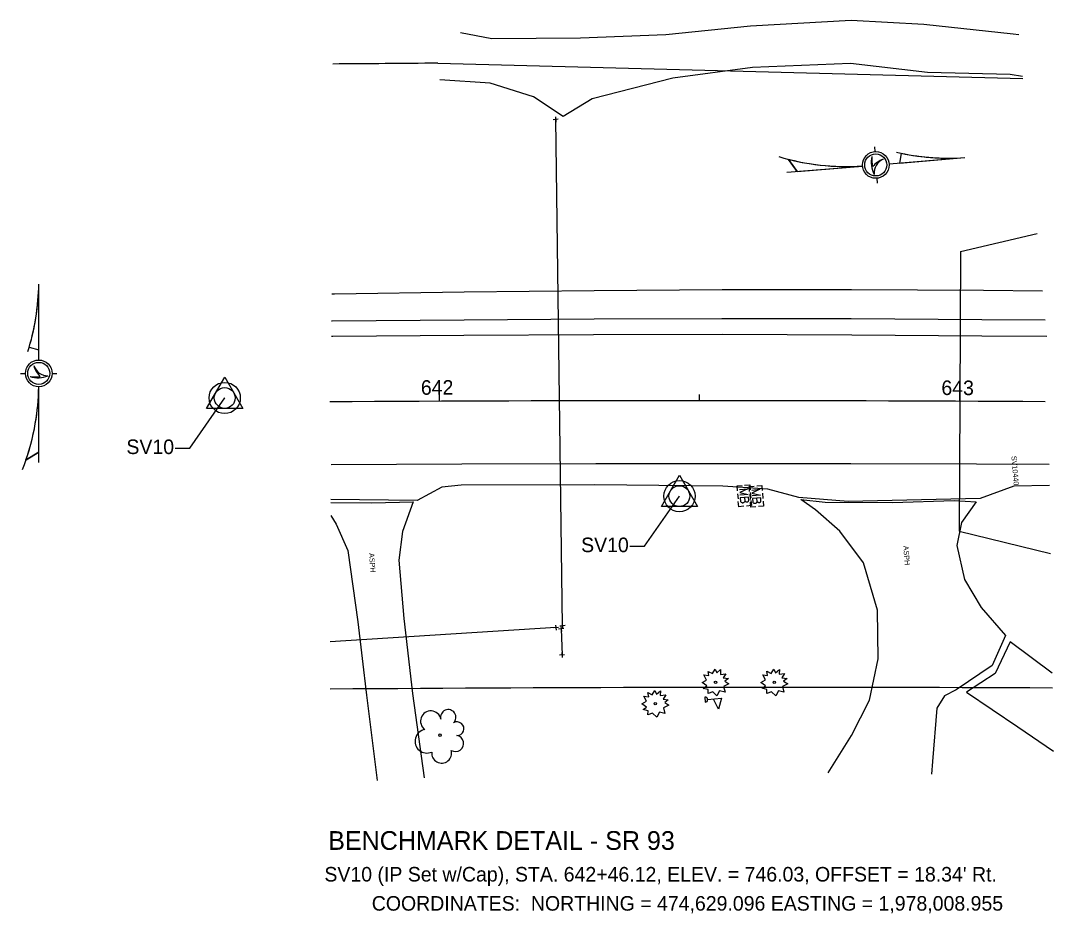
# Model space of a CAD drawing. Extents: x 0 to 2009, y -63 to 801.
# Drawn here: x 698.2 to 896.7, y 252.2 to 423.9 of the extents above; entities that cross this region are included whole.
import ezdxf

# ---------------------------------------------------------------- set-up
doc = ezdxf.new("R2010")
doc.units = 0
for name, color, linetype in [('Default', 7, 'Continuous'), ('DR_X_Elev_Flow', 7, 'Continuous'), ('DR_X_Storm_Sewer', 7, 'Continuous'), ('DV_X_Section_VMS_Line', 7, 'Continuous'), ('HY_X_Water_Edge', 7, 'Continuous'), ('PF_X_Text', 7, 'Continuous'), ('PV_X_Driveway', 7, 'Continuous'), ('PV_X_Shoulder', 7, 'Continuous'), ('PV_X_Shoulder_Aggregate', 7, 'Continuous'), ('PV_X_Text', 7, 'Continuous'), ('RD_X_Cells', 7, 'Continuous'), ('RD_X_GR_Lt', 7, 'Continuous'), ('RW_P_Const_Limits', 7, 'Continuous'), ('RW_X_CL_500_Stations', 7, 'Continuous'), ('RW_X_Esmt_SH', 7, 'Continuous'), ('SV_P_Control_Cells_Set', 7, 'Continuous'), ('SV_X_Control_Cells_Found', 7, 'Continuous'), ('TX_P_1', 7, 'Continuous'), ('UT_X_Electric', 7, 'Continuous'), ('UT_X_Electric_Cells', 7, 'Continuous'), ('VG_X_Cells', 7, 'Continuous')]:
    doc.layers.add(name, color=color, linetype=linetype)

msp = doc.modelspace()

# ---------------------------------------------------------------- linework, layer by layer
at = {"layer": 'Default'}
for p, q in [((730.73, 341.71), (737.42, 351.34)), ((727.91, 341.71), (730.73, 341.71)), ((818.12, 322.85), (824.8, 332.47)), ((815.3, 322.85), (818.12, 322.85))]:
    msp.add_line(p, q, dxfattribs=at)
at = {"layer": 'DR_X_Elev_Flow'}
for points in [[(895.1, 366.33), (882.95, 366.37), (857.78, 366.57), (832.95, 366.55), (808.41, 366.52), (783.46, 366.31), (758.09, 366.09), (757.96, 366.09)], [(895.91, 334.5), (889.06, 334.41), (882.58, 332), (857.24, 331.41), (847.74, 332.18), (841.82, 333.81), (833.16, 334.37), (808.52, 334.66), (782.86, 334.55), (779.12, 334.2), (774.42, 331.65), (757.82, 331.79)]]:
    msp.add_lwpolyline(points, dxfattribs=at)
at = {"layer": 'DV_X_Section_VMS_Line'}
for p, q in [((835.99, 332.93), (836.08, 331.94)), ((837.25, 332.52), (837.25, 332.52)), ((838.33, 332.82), (838.41, 331.82)), ((838.43, 333.13), (838.51, 332.14)), ((839.59, 332.41), (839.59, 332.41)), ((840.77, 333.02), (840.85, 332.02)), ((829.69, 293.82), (829.77, 292.82)), ((830.23, 293.36), (832.92, 293.58)), ((832.29, 291.52), (831.33, 293.45)), ((831.33, 293.45), (831.33, 293.45)), ((832.92, 293.58), (832.29, 291.52))]:
    msp.add_line(p, q, dxfattribs=at)
for points in [[(835.95, 333.45), (835.87, 334.42), (836.84, 334.5)], [(836.35, 333.75), (837.94, 333.88), (836.4, 333.17), (838.04, 332.75), (836.44, 332.62)], [(837.34, 334.54), (838.31, 334.62), (838.39, 333.65)], [(838.29, 333.34), (838.21, 334.31), (839.18, 334.38)], [(838.69, 333.64), (840.28, 333.77), (838.73, 333.06), (840.37, 332.64), (838.78, 332.51)], [(839.68, 334.43), (840.64, 334.51), (840.72, 333.54)], [(837.41, 331.51), (837.47, 331.45), (837.51, 331.42), (837.55, 331.4), (837.58, 331.39), (837.63, 331.37), (837.67, 331.36), (837.76, 331.34), (837.8, 331.34), (837.85, 331.35), (837.92, 331.36), (837.98, 331.39), (838.03, 331.44), (838.08, 331.5), (838.1, 331.56), (838.11, 331.58), (838.13, 331.65), (838.08, 332.26), (836.48, 332.13), (836.54, 331.44), (836.6, 331.36), (836.67, 331.29), (836.77, 331.23), (836.89, 331.2), (837, 331.2), (837.08, 331.21), (837.15, 331.24), (837.26, 331.3), (837.33, 331.37), (837.41, 331.51), (837.35, 332.2)], [(838.55, 331.62), (838.63, 330.63), (837.67, 330.55)], [(839.74, 331.4), (839.81, 331.34), (839.85, 331.31), (839.89, 331.29), (839.92, 331.28), (839.97, 331.25), (840.01, 331.24), (840.1, 331.23), (840.14, 331.23), (840.19, 331.23), (840.26, 331.25), (840.32, 331.28), (840.37, 331.32), (840.41, 331.39), (840.44, 331.44), (840.45, 331.47), (840.47, 331.53), (840.42, 332.15), (838.82, 332.02), (838.88, 331.33), (838.93, 331.24), (839, 331.17), (839.11, 331.12), (839.23, 331.09), (839.34, 331.09), (839.42, 331.09), (839.49, 331.13), (839.6, 331.19), (839.67, 331.25), (839.74, 331.4), (839.69, 332.09)], [(840.89, 331.51), (840.97, 330.52), (840.01, 330.44)], [(837.17, 330.51), (836.2, 330.43), (836.12, 331.42)], [(839.5, 330.4), (838.54, 330.32), (838.46, 331.31)]]:
    msp.add_lwpolyline(points, dxfattribs=at)
msp.add_arc((829.73, 293.32), 0.5, 274.7026, 94.7026, dxfattribs=at)
at = {"layer": 'HY_X_Water_Edge'}
for points in [[(890, 421.17), (888.92, 421.32), (871.76, 423.14), (857.82, 423.9), (838.49, 422.85), (822.22, 421.16), (805.82, 420.5), (788.73, 420.42), (782.75, 421.56)], [(890.74, 413.14), (888.34, 413.55), (872.46, 413.93), (857.65, 415.66), (838.86, 414.92), (823.54, 412.87), (808.05, 408.85), (802.44, 405.47), (796.74, 409.26), (788.44, 411.88), (778.78, 412.52)]]:
    msp.add_lwpolyline(points, dxfattribs=at)
at = {"layer": 'PF_X_Text'}
for points in [[(895.4, 363.17), (882.94, 363.2), (857.93, 363.43), (833.09, 363.52), (808.32, 363.48), (783.38, 363.33), (758.19, 363.16), (757.95, 363.15)], [(895.85, 338.52), (881.92, 338.58), (857.75, 338.7), (833.62, 338.7), (808.72, 338.65), (783, 338.64), (757.85, 338.49)]]:
    msp.add_lwpolyline(points, dxfattribs=at)
at = {"layer": 'PV_X_Shoulder'}
for centre in [(737.42, 351.34), (824.8, 332.47)]:
    msp.add_circle(centre, 3, dxfattribs=at)
at = {"layer": 'PV_X_Shoulder_Aggregate'}
for p, q in [((862.26, 399.63), (862.33, 398.72)), ((847.44, 394.91), (845.77, 397.23)), ((865.11, 396.36), (879.65, 397.56)), ((867.41, 398.38), (867.07, 396.52)), ((845.44, 394.74), (859.98, 395.94)), ((862.76, 393.59), (862.83, 392.67)), ((701.69, 358.65), (701.69, 373.23)), ((699.87, 361.11), (701.69, 360.61)), ((698.2, 356.07), (699.12, 356.07)), ((704.27, 356.07), (705.18, 356.07)), ((701.69, 338.91), (701.69, 353.5)), ((701.69, 340.91), (699.24, 339.44))]:
    msp.add_line(p, q, dxfattribs=at)
for points in [[(845.77, 397.23), (847.44, 394.91), (859.98, 395.94)], [(867.42, 398.39), (867.41, 398.38), (867.07, 396.52), (879.65, 397.56)], [(699.86, 361.11), (699.87, 361.11), (701.69, 360.61), (701.69, 373.23)], [(699.24, 339.44), (701.69, 340.91), (701.69, 353.5)]]:
    msp.add_lwpolyline(points, dxfattribs=at)
for centre, radius in [((862.54, 396.15), 2.57), ((862.54, 396.15), 2.12), ((701.69, 356.07), 2.57), ((701.69, 356.07), 2.12)]:
    msp.add_circle(centre, radius, dxfattribs=at)
for centre, radius, start, end in [((856.91, 440.94), 45.1, 253.208, 273.8973), ((856.91, 440.94), 45.1, 255.6963, 273.8973), ((866.85, 396.63), 5.18, 167.19, 206.1886), ((868.32, 397.26), 6.54, 175.4303, 192.5761), ((865.18, 393.31), 4.1, 107.5583, 142.0168), ((865.12, 394.56), 2.92, 113.8601, 184.0736), ((876.58, 442.56), 45.1, 257.1179, 273.8973), ((876.58, 442.56), 45.1, 258.278, 273.8973), ((656.59, 373.87), 45.1, 342.4153, 359.1947), ((656.59, 373.87), 45.1, 343.5754, 359.1947), ((703.49, 358.51), 2.92, 199.1575, 269.3709), ((704.74, 358.46), 4.1, 192.8556, 227.3141), ((701.57, 360.41), 5.18, 252.4874, 291.486), ((701.06, 361.92), 6.54, 260.7277, 277.8734), ((656.59, 354.13), 45.1, 338.5054, 359.1947), ((656.59, 354.13), 45.1, 340.9936, 359.1947)]:
    msp.add_arc(centre, radius, start, end, dxfattribs=at)
at = {"layer": 'RD_X_Cells'}
msp.add_lwpolyline([(757.99, 371.34), (758.52, 371.34), (783.45, 371.77), (808.39, 372.03), (833.02, 372.22), (857.89, 372.19), (883.23, 372.05), (894.58, 371.94)], dxfattribs=at)
at = {"layer": 'RD_X_GR_Lt'}
for points in [[(853.36, 279.28), (857.86, 286.45), (861.32, 293.21), (862.97, 301.16), (862.89, 310.52), (860.16, 319.66), (855.66, 325.7), (850.93, 329.84), (848.12, 331.83), (852.8, 331.28), (865.78, 331.23), (877.63, 331.62), (881.8, 331.39), (879.03, 327.4), (878.11, 322.97), (879.61, 316.45), (882.78, 311.07), (887.44, 305.69), (884.93, 299.89), (877.97, 295.21), (875.76, 294.03), (874.27, 291.67), (873.47, 281.44), (873.27, 279.02)], [(757.82, 331.26), (765.66, 331.17), (773.64, 331.36), (771.59, 325.69), (770.86, 320.13), (771.87, 308.93), (773.49, 294.53), (775.77, 278.29)], [(757.81, 328.76), (758.85, 327.05), (761.1, 322), (763.03, 308.31), (764.69, 294.16), (766.73, 277.75)], [(896.44, 298.42), (888.37, 304.42), (885.48, 298.37), (879.98, 294.78)], [(879.98, 294.78), (889.85, 288.11), (896.66, 283.42)]]:
    msp.add_lwpolyline(points, dxfattribs=at)
at = {"layer": 'RW_P_Const_Limits'}
for p, q in [((778.68, 350.7), (778.67, 351.9)), ((878.68, 350.7), (878.68, 351.9))]:
    msp.add_line(p, q, dxfattribs=at)
at = {"layer": 'RW_X_CL_500_Stations'}
for p, q in [((878.8, 379.5), (893.56, 382.95)), ((878.8, 379.5), (878.68, 350.7)), ((878.68, 350.7), (878.57, 325.71)), ((878.57, 325.71), (896.1, 321.46))]:
    msp.add_line(p, q, dxfattribs=at)
at = {"layer": 'RW_X_Esmt_SH'}
for points in [[(833.53, 296.88), (834.31, 296.34), (833.3, 295.84), (833.57, 294.76), (832.53, 295.02), (832.02, 294.03), (831.21, 294.82), (830.32, 294.5), (830.33, 295.25), (829.39, 295.5), (830.05, 295.99), (829.18, 296.6), (830.03, 297.1), (829.51, 298.08), (830.47, 297.96), (830.32, 298.76), (831.15, 298.36), (831.65, 299.17), (831.97, 298.46), (832.72, 299.13), (832.69, 298.19), (833.72, 298.3), (833.22, 297.51), (834.22, 297.38), (833.53, 296.88)], [(844.83, 296.9), (845.61, 296.36), (844.6, 295.86), (844.86, 294.79), (843.83, 295.04), (843.31, 294.05), (842.51, 294.85), (841.62, 294.52), (841.63, 295.28), (840.69, 295.53), (841.34, 296.01), (840.47, 296.62), (841.32, 297.12), (840.81, 298.1), (841.76, 297.99), (841.62, 298.79), (842.44, 298.38), (842.94, 299.19), (843.27, 298.48), (844.02, 299.15), (843.99, 298.21), (845.02, 298.33), (844.51, 297.53), (845.51, 297.41), (844.83, 296.9)], [(821.97, 292.8), (822.75, 292.25), (821.73, 291.75), (822, 290.68), (820.97, 290.94), (820.45, 289.94), (819.65, 290.74), (818.76, 290.41), (818.77, 291.17), (817.83, 291.42), (818.48, 291.9), (817.61, 292.51), (818.46, 293.01), (817.95, 293.99), (818.9, 293.88), (818.75, 294.68), (819.58, 294.27), (820.08, 295.09), (820.41, 294.37), (821.16, 295.04), (821.13, 294.11), (822.16, 294.22), (821.65, 293.42), (822.65, 293.3), (821.97, 292.8)]]:
    msp.add_lwpolyline(points, dxfattribs=at)
for centre, radius in [((831.74, 296.65), 0.23), ((843.03, 296.67), 0.23), ((820.17, 292.56), 0.23), ((778.8, 286.49), 0.24)]:
    msp.add_circle(centre, radius, dxfattribs=at)
for centre, radius, start, end in [((777.02, 289.2), 1.97, 10.8748, 235.2764), ((780.38, 289.94), 1.47, 313.7652, 194.2439), ((782.07, 287.74), 1.32, 268.7073, 120.6768), ((776.28, 285.33), 2.28, 99.6502, 294.1598), ((781.77, 284.9), 1.55, 238.5326, 79.7402), ((779.12, 283.04), 1.91, 173.848, 16.1623)]:
    msp.add_arc(centre, radius, start, end, dxfattribs=at)
at = {"layer": 'SV_X_Control_Cells_Found'}
for p, q in [((802.32, 307.52), (801.03, 404.89)), ((801.06, 307.18), (757.71, 304.46)), ((802.08, 306.95), (802.24, 301.9))]:
    msp.add_line(p, q, dxfattribs=at)
at = {"layer": 'TX_P_1'}
msp.add_line((778.39, 415.7), (890.78, 412.77), dxfattribs=at)
for centre, radius, start, end in [((857.33, -11108.18), 11524.16, 90.392452, 90.493001), ((844.86, -11028.37), 11324.05, 89.738791, 90.441133)]:
    msp.add_arc(centre, radius, start, end, dxfattribs=at)
at = {"layer": 'UT_X_Electric'}
for p, q in [((778.68, 350.7), (778.67, 352.7)), ((828.68, 350.81), (828.68, 352.01)), ((878.68, 350.7), (878.68, 352.7))]:
    msp.add_line(p, q, dxfattribs=at)
msp.add_arc((828.67, -11108.35), 11459.16, 89.668, 90.355187, dxfattribs=at)
at = {"layer": 'UT_X_Electric_Cells'}
for p, q in [((737.42, 351.34), (737.42, 351.34)), ((824.8, 332.47), (824.8, 332.47))]:
    msp.add_line(p, q, dxfattribs=at)
for points in [[(733.95, 349.34), (737.42, 355.34), (740.88, 349.34)], [(821.34, 330.47), (824.8, 336.47), (828.27, 330.47)]]:
    msp.add_lwpolyline(points, close=True, dxfattribs=at)
for centre in [(737.42, 351.34), (824.8, 332.47)]:
    msp.add_circle(centre, 2, dxfattribs=at)
at = {"layer": 'VG_X_Cells'}
for p, q in [((801.52, 404.93), (800.53, 404.85)), ((800.98, 405.39), (801.07, 404.39)), ((801.03, 404.89), (801.03, 404.89)), ((801.02, 307.68), (801.1, 306.68)), ((802.28, 308.02), (802.36, 307.02)), ((801.56, 307.22), (800.56, 307.14)), ((801.06, 307.18), (801.06, 307.18)), ((802.58, 306.99), (801.58, 306.91)), ((802.82, 307.56), (801.82, 307.48)), ((802.04, 307.45), (802.12, 306.45)), ((802.08, 306.95), (802.08, 306.95)), ((802.32, 307.52), (802.32, 307.52)), ((802.74, 301.94), (801.74, 301.86)), ((802.2, 302.4), (802.28, 301.4)), ((802.24, 301.9), (802.24, 301.9))]:
    msp.add_line(p, q, dxfattribs=at)

# ---------------------------------------------------------------- texts
at = {"layer": 'Default'}
for p in [(718.53, 340.55), (805.91, 321.69)]:
    msp.add_text('SV10', height=2.8, dxfattribs=at).set_placement(p)
at = {"layer": 'DR_X_Storm_Sewer'}
msp.add_text('SV10440', height=1, rotation=274.7026, dxfattribs=at).set_placement((888.59, 340.15))
at = {"layer": 'PV_X_Driveway'}
for s, p in [("SV10 (IP Set w/Cap), STA. 642+46.12, ELEV. = 746.03, OFFSET = 18.34' Rt.", (756.58, 258.35)), ('COORDINATES:  NORTHING = 474,629.096 EASTING = 1,978,008.955', (765.68, 252.75))]:
    msp.add_text(s, height=2.8, dxfattribs=at).set_placement(p)
at = {"layer": 'PV_X_Text'}
for p in [(867.81, 322.89), (765.14, 321.48)]:
    msp.add_text('ASPH', height=1, rotation=274.7026, dxfattribs=at).set_placement(p)
at = {"layer": 'SV_P_Control_Cells_Set'}
msp.add_text('BENCHMARK DETAIL - SR 93', height=3.6, dxfattribs=at).set_placement((757.31, 264.44))
at = {"layer": 'UT_X_Electric'}
for s, rotation, p in [('642', 0.25, (775.12, 351.95)), ('643', 359.75, (875.14, 351.91))]:
    msp.add_text(s, height=2.8, rotation=rotation, dxfattribs=at).set_placement(p)

doc.saveas('drawing.dxf')
